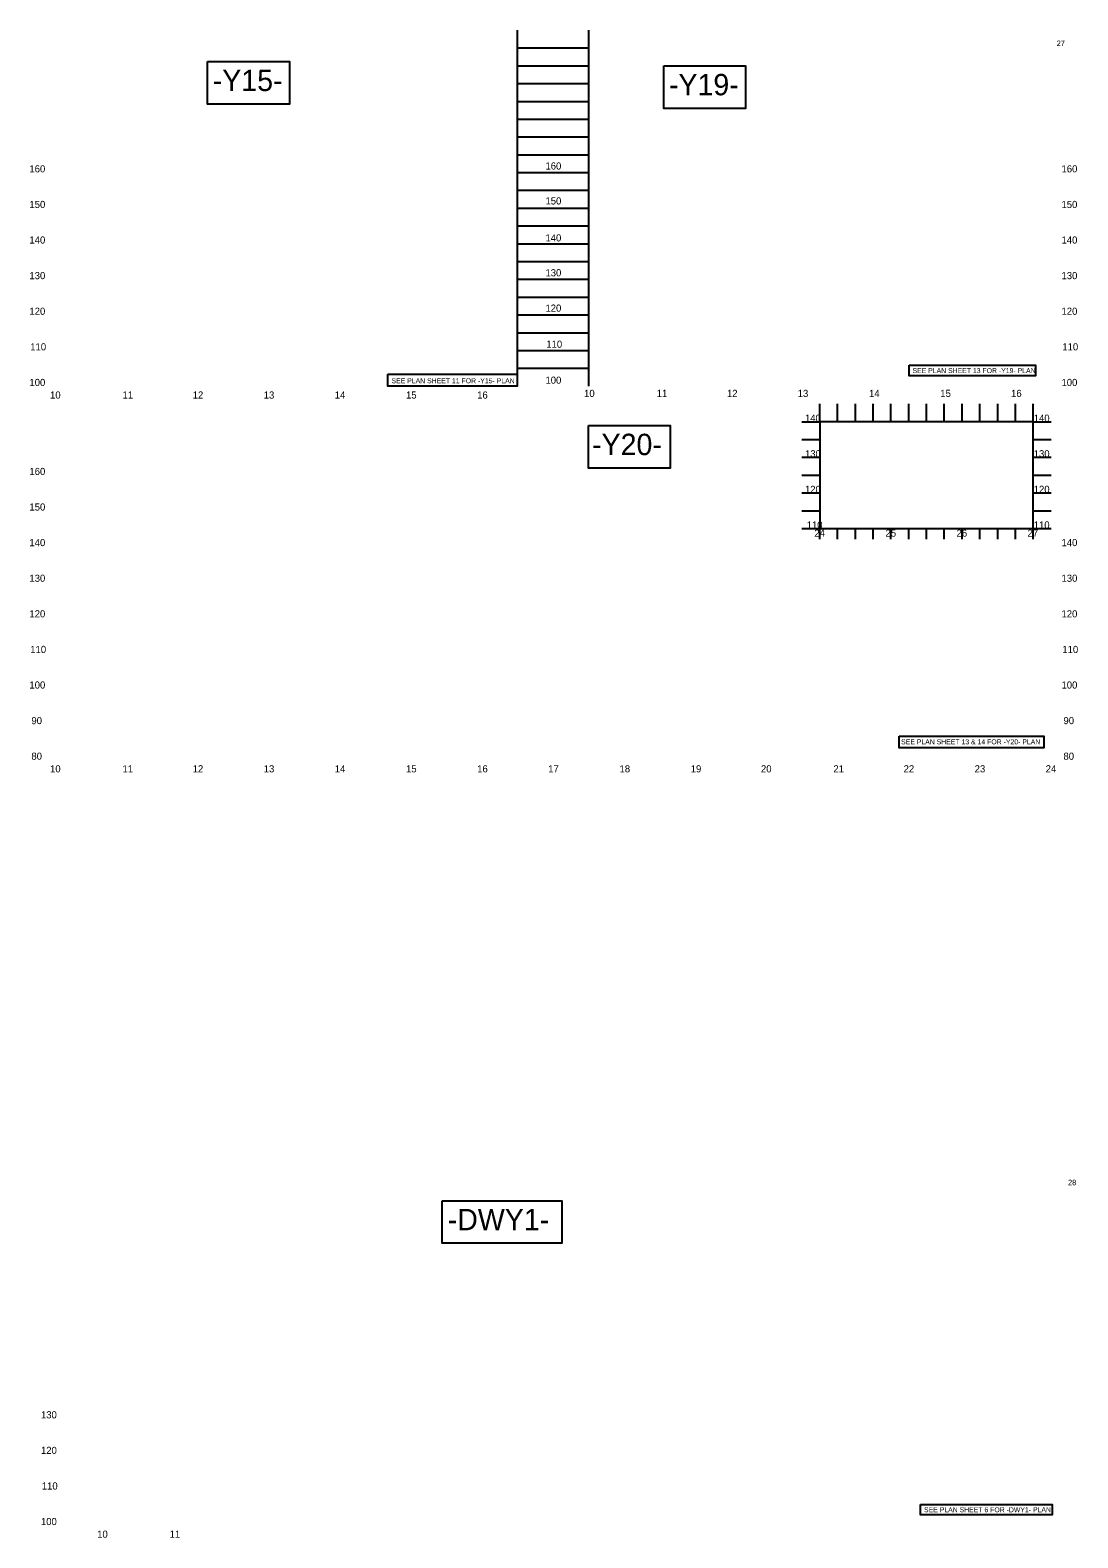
# Model space of a CAD drawing. Extents: x 2364289 to 2366249, y 588759 to 610062.
# Drawn here: x 2364496 to 2365968, y 588759 to 590876 of the extents above; entities that cross this region are included whole.
import ezdxf

# ---------------------------------------------------------------- set-up
doc = ezdxf.new("R2010")
doc.units = 0
for name, color, linetype in [('Exist Vertical Profile Horizontal Axis Label Major', 7, 'Continuous'), ('Exist Vertical Profile Vertical Axis Label', 7, 'Continuous'), ('Prop DSN Text', 7, 'Continuous'), ('Prop Grid Mask', 7, 'Continuous'), ('Sheet Data Field CELL', 7, 'Continuous'), ('Sheet Profile CELL', 7, 'Continuous'), ('Sheet Profile Grid Major CELL', 7, 'Continuous'), ('Sheet Profile Grid Middle CELL', 7, 'Continuous')]:
    doc.layers.add(name, color=color, linetype=linetype)

msp = doc.modelspace()

# ---------------------------------------------------------------- linework, layer by layer
at = {"layer": 'Prop Grid Mask'}
for points in [[(2364745.7, 590832.4), (2364860.8, 590832.4), (2364860.8, 590772.6), (2364745.7, 590772.6)], [(2365386.8, 590826.5), (2365501.5, 590826.5), (2365501.5, 590766.6), (2365386.8, 590766.6)], [(2365731.2, 590405.7), (2365908.8, 590405.7), (2365908.8, 590391.1), (2365731.2, 590391.1)], [(2364999, 590393.4), (2365180.8, 590393.4), (2365180.8, 590376.5), (2364999, 590376.5)], [(2365280.8, 590321.1), (2365395.5, 590321.1), (2365395.5, 590261.3), (2365280.8, 590261.3)], [(2365717.5, 589885), (2365920.7, 589885), (2365920.7, 589868.3), (2365717.5, 589868.3)], [(2365075.5, 589232.4), (2365243.4, 589232.4), (2365243.4, 589172.6), (2365075.5, 589172.6)], [(2365747.4, 588805.7), (2365932.1, 588805.7), (2365932.1, 588791.1), (2365747.4, 588791.1)]]:
    msp.add_lwpolyline(points, close=True, dxfattribs=at)
at = {"layer": 'Sheet Profile CELL'}
for p, q in [((2365180.8, 590876.5), (2365180.8, 590376.5)), ((2365280.8, 590876.5), (2365280.8, 590376.5))]:
    msp.add_line(p, q, dxfattribs=at)
msp.add_lwpolyline([(2365905.8, 590326.5), (2365605.8, 590326.5), (2365605.8, 590176.5), (2365905.8, 590176.5)], close=True, dxfattribs=at)
at = {"layer": 'Sheet Profile Grid Major CELL'}
for p, q in [((2365180.8, 590826.5), (2365280.8, 590826.5)), ((2365180.8, 590776.5), (2365280.8, 590776.5)), ((2365180.8, 590726.5), (2365280.8, 590726.5)), ((2365180.8, 590676.5), (2365280.8, 590676.5)), ((2365180.8, 590626.5), (2365280.8, 590626.5)), ((2365180.8, 590576.5), (2365280.8, 590576.5)), ((2365180.8, 590526.5), (2365280.8, 590526.5)), ((2365180.8, 590476.5), (2365280.8, 590476.5)), ((2365180.8, 590426.5), (2365280.8, 590426.5)), ((2365630.8, 590326.5), (2365630.8, 590351.5)), ((2365680.8, 590326.5), (2365680.8, 590351.5)), ((2365730.8, 590326.5), (2365730.8, 590351.5)), ((2365780.8, 590326.5), (2365780.8, 590351.5)), ((2365830.8, 590326.5), (2365830.8, 590351.5)), ((2365880.8, 590326.5), (2365880.8, 590351.5)), ((2365580.8, 590301.5), (2365605.8, 590301.5)), ((2365905.8, 590301.5), (2365930.8, 590301.5)), ((2365580.8, 590251.5), (2365605.8, 590251.5)), ((2365905.8, 590251.5), (2365930.8, 590251.5)), ((2365580.8, 590201.5), (2365605.8, 590201.5)), ((2365905.8, 590201.5), (2365930.8, 590201.5)), ((2365630.8, 590161.5), (2365630.8, 590176.5)), ((2365680.8, 590161.5), (2365680.8, 590176.5)), ((2365730.8, 590161.5), (2365730.8, 590176.5)), ((2365780.8, 590161.5), (2365780.8, 590176.5)), ((2365830.8, 590161.5), (2365830.8, 590176.5)), ((2365880.8, 590161.5), (2365880.8, 590176.5))]:
    msp.add_line(p, q, dxfattribs=at)
at = {"layer": 'Sheet Profile Grid Middle CELL'}
for p, q in [((2365180.8, 590851.5), (2365280.8, 590851.5)), ((2365180.8, 590801.5), (2365280.8, 590801.5)), ((2365180.8, 590751.5), (2365280.8, 590751.5)), ((2365180.8, 590701.5), (2365280.8, 590701.5)), ((2365180.8, 590651.5), (2365280.8, 590651.5)), ((2365180.8, 590601.5), (2365280.8, 590601.5)), ((2365180.8, 590551.5), (2365280.8, 590551.5)), ((2365180.8, 590501.5), (2365280.8, 590501.5)), ((2365180.8, 590451.5), (2365280.8, 590451.5)), ((2365180.8, 590401.5), (2365280.8, 590401.5)), ((2365605.8, 590326.5), (2365605.8, 590351.5)), ((2365655.8, 590326.5), (2365655.8, 590351.5)), ((2365705.8, 590326.5), (2365705.8, 590351.5)), ((2365755.8, 590326.5), (2365755.8, 590351.5)), ((2365805.8, 590326.5), (2365805.8, 590351.5)), ((2365855.8, 590326.5), (2365855.8, 590351.5)), ((2365905.8, 590326.5), (2365905.8, 590351.5)), ((2365580.8, 590326.5), (2365605.8, 590326.5)), ((2365905.8, 590326.5), (2365930.8, 590326.5)), ((2365580.8, 590276.5), (2365605.8, 590276.5)), ((2365905.8, 590276.5), (2365930.8, 590276.5)), ((2365580.8, 590226.5), (2365605.8, 590226.5)), ((2365905.8, 590226.5), (2365930.8, 590226.5)), ((2365580.8, 590176.5), (2365605.8, 590176.5)), ((2365605.8, 590161.5), (2365605.8, 590176.5)), ((2365655.8, 590161.5), (2365655.8, 590176.5)), ((2365705.8, 590161.5), (2365705.8, 590176.5)), ((2365755.8, 590161.5), (2365755.8, 590176.5)), ((2365805.8, 590161.5), (2365805.8, 590176.5)), ((2365855.8, 590161.5), (2365855.8, 590176.5)), ((2365905.8, 590161.5), (2365905.8, 590176.5)), ((2365905.8, 590176.5), (2365930.8, 590176.5))]:
    msp.add_line(p, q, dxfattribs=at)

# ---------------------------------------------------------------- texts
at = {"layer": 'Exist Vertical Profile Horizontal Axis Label Major'}
for s, p in [('10', (2364524.4, 590359)), ('11', (2364626.2, 590359)), ('12', (2364724.8, 590359)), ('13', (2364824.6, 590359)), ('14', (2364924.4, 590359)), ('15', (2365024.5, 590359)), ('16', (2365124.5, 590359)), ('10', (2365274.7, 590361.3)), ('11', (2365376.7, 590361.3)), ('12', (2365475.4, 590361.3)), ('13', (2365574.8, 590361.3)), ('14', (2365675.1, 590361.3)), ('15', (2365775.1, 590361.3)), ('16', (2365874.6, 590361.3)), ('24', (2365598.2, 590165)), ('25', (2365698.2, 590165)), ('26', (2365798, 590165)), ('27', (2365897.7, 590165)), ('10', (2364524.4, 589834)), ('11', (2364626.2, 589834)), ('12', (2364724.8, 589834)), ('13', (2364824.6, 589834)), ('14', (2364924.4, 589834)), ('15', (2365024.5, 589834)), ('16', (2365124.5, 589834)), ('17', (2365224.3, 589834)), ('18', (2365324.5, 589834)), ('19', (2365424.5, 589834)), ('20', (2365523.2, 589834)), ('21', (2365625, 589834)), ('22', (2365723.6, 589834)), ('23', (2365823.4, 589834)), ('24', (2365923.2, 589834)), ('10', (2364590.6, 588759)), ('11', (2364692.4, 588759))]:
    msp.add_text(s, height=10, dxfattribs=at).set_placement(p)
at = {"layer": 'Exist Vertical Profile Vertical Axis Label'}
for s, p in [('160', (2364495.4, 590676.7)), ('160', (2365220.4, 590680.7)), ('160', (2365945.4, 590676.7)), ('150', (2364495.4, 590626.7)), ('150', (2365220.4, 590631.6)), ('150', (2365945.4, 590626.7)), ('140', (2365220.4, 590579.7)), ('140', (2364495.4, 590576.7)), ('140', (2365945.4, 590576.7)), ('130', (2364495.4, 590526.7)), ('130', (2365220.4, 590530.7)), ('130', (2365945.4, 590526.7)), ('120', (2364495.4, 590476.7)), ('120', (2365220.4, 590481.1)), ('120', (2365945.4, 590476.7)), ('110', (2364496.6, 590426.7)), ('110', (2365221.6, 590430.4)), ('110', (2365946.6, 590426.7)), ('100', (2364495.4, 590376.7)), ('100', (2365220.4, 590379.9)), ('100', (2365945.4, 590376.7)), ('140', (2365585, 590326.5)), ('140', (2365906.4, 590326.5)), ('130', (2365585, 590276.5)), ('130', (2365906.4, 590276.5)), ('160', (2364495.4, 590251.7)), ('120', (2365585, 590226.5)), ('120', (2365906.4, 590226.5)), ('150', (2364495.4, 590201.7)), ('110', (2365587.4, 590176.5)), ('110', (2365906.4, 590176.5)), ('140', (2364495.4, 590151.7)), ('140', (2365945.4, 590151.7)), ('130', (2364495.4, 590101.7)), ('130', (2365945.4, 590101.7)), ('120', (2364495.4, 590051.7)), ('120', (2365945.4, 590051.7)), ('110', (2364496.6, 590001.7)), ('110', (2365946.6, 590001.7)), ('100', (2364495.4, 589951.7)), ('100', (2365945.4, 589951.7)), ('90', (2364498.2, 589901.7)), ('90', (2365948.2, 589901.7)), ('80', (2364498.2, 589851.7)), ('80', (2365948.2, 589851.7)), ('130', (2364511.6, 588926.7)), ('120', (2364511.6, 588876.7)), ('110', (2364512.8, 588826.7)), ('100', (2364511.6, 588776.7))]:
    msp.add_text(s, height=10, dxfattribs=at).set_placement(p)
at = {"layer": 'Prop DSN Text'}
for s, p in [('SEE PLAN SHEET 13 FOR -Y19- PLAN', (2365736.1, 590394.8)), ('SEE PLAN SHEET 11 FOR -Y15- PLAN', (2365004.2, 590380.5)), ('SEE PLAN SHEET 13 & 14 FOR -Y20- PLAN', (2365720.1, 589873.4)), ('SEE PLAN SHEET 6 FOR -DWY1- PLAN', (2365752.3, 588794.8))]:
    msp.add_text(s, height=7, dxfattribs=at).set_placement(p)
at = {"layer": 'Prop Grid Mask'}
for s, p in [('-Y15-', (2364753, 590790.9)), ('-Y19-', (2365393.9, 590785)), ('-Y20-', (2365285.9, 590279.6)), ('-DWY1-', (2365083.1, 589190.9))]:
    msp.add_text(s, height=30, dxfattribs=at).set_placement(p)
at = {"layer": 'Sheet Data Field CELL'}
for s, p in [('27', (2365938.7, 590854.1)), ('28', (2365954.6, 589254.1))]:
    msp.add_text(s, height=7.75, dxfattribs=at).set_placement(p)

doc.saveas('drawing.dxf')
